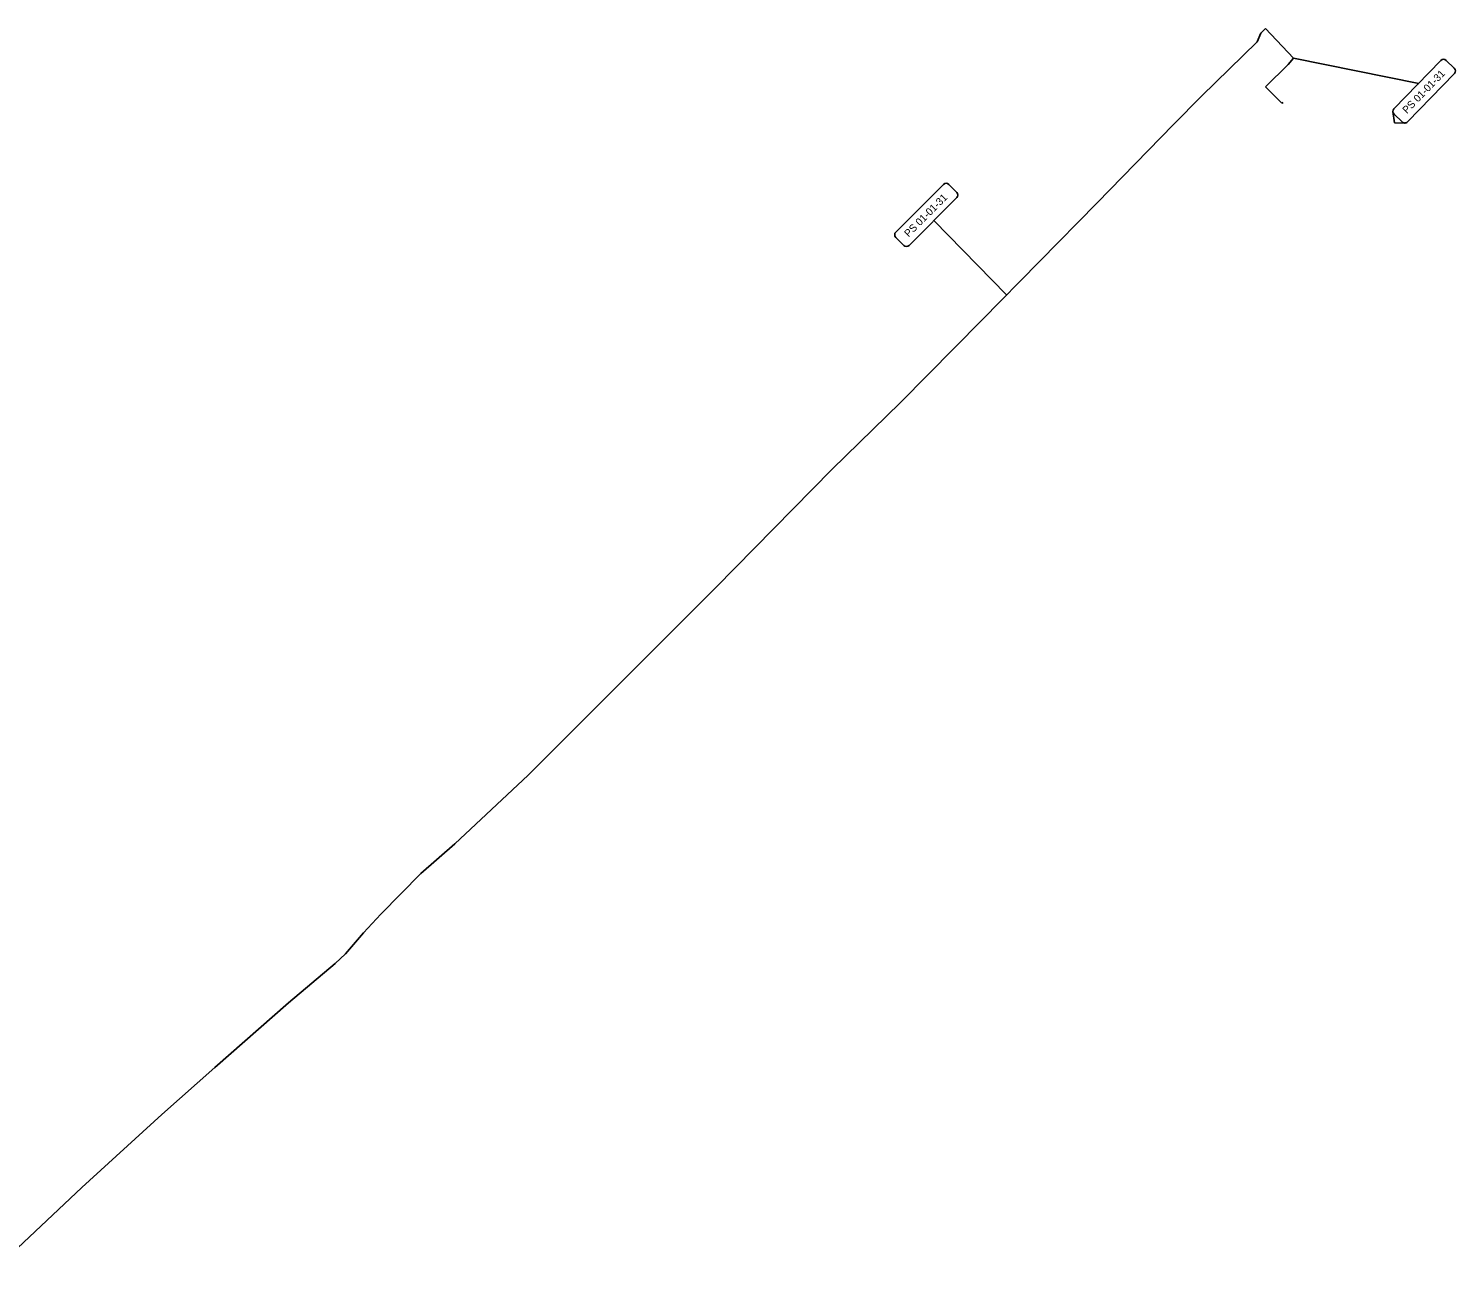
# Model space of a CAD drawing. Extents: x -541464 to -539952, y -1188799 to -1187382.
# Drawn here: x -540701 to -539952, y -1188031 to -1187382 of the extents above; entities that cross this region are included whole.
import ezdxf

# ---------------------------------------------------------------- set-up
doc = ezdxf.new("R2010")
doc.units = 0
doc.layers.add('PS 01-01-31', color=7, linetype='Continuous')

msp = doc.modelspace()

# ---------------------------------------------------------------- linework, layer by layer
at = {"layer": 'PS 01-01-31'}
for p, q in [((-540053.796, -1187384.014), (-540055.837, -1187388.607)), ((-540051.349, -1187381.646), (-540053.796, -1187384.014)), ((-540036.708, -1187397.239), (-540051.349, -1187381.646)), ((-540055.837, -1187388.607), (-540085.066, -1187417.093)), ((-540051.412, -1187412.276), (-540039.488, -1187400.592)), ((-540039.488, -1187400.592), (-540036.708, -1187397.239)), ((-539970.911, -1187410.448), (-540036.708, -1187397.239)), ((-539983.905, -1187423.848), (-539959.24, -1187398.41)), ((-539956.456, -1187398.367), (-539952.216, -1187402.477)), ((-539952.173, -1187405.261), (-539976.838, -1187430.7)), ((-540085.066, -1187417.093), (-540099.657, -1187432.125)), ((-540049.541, -1187414.224), (-540051.412, -1187412.276)), ((-540042.881, -1187420.898), (-540049.541, -1187414.224)), ((-540042.136, -1187420.439), (-540042.881, -1187420.898)), ((-539984.46, -1187425.249), (-539983.663, -1187431.106)), ((-540099.657, -1187432.125), (-540139.811, -1187473.137)), ((-539979.622, -1187430.743), (-539983.861, -1187426.632)), ((-539983.663, -1187431.106), (-539978.221, -1187431.298)), ((-540245.598, -1187488.587), (-540220.537, -1187463.538)), ((-540213.579, -1187470.5), (-540238.641, -1187495.548)), ((-540217.753, -1187463.539), (-540213.578, -1187467.716)), ((-540139.811, -1187473.137), (-540200.425, -1187534.795)), ((-540225.555, -1187482.469), (-540187.374, -1187521.52)), ((-540241.425, -1187495.548), (-540245.599, -1187491.37)), ((-540200.425, -1187534.795), (-540243.107, -1187578.127)), ((-540243.107, -1187578.127), (-540279.202, -1187613.271)), ((-540279.202, -1187613.271), (-540340.21, -1187675.277)), ((-540340.21, -1187675.277), (-540403.608, -1187738.906)), ((-540403.608, -1187738.906), (-540438.749, -1187773.95)), ((-540438.749, -1187773.95), (-540477.233, -1187810.058)), ((-540477.233, -1187810.058), (-540495.127, -1187825.49)), ((-540495.127, -1187825.49), (-540516.103, -1187846.952)), ((-540516.103, -1187846.952), (-540525.206, -1187856.697)), ((-540525.206, -1187856.697), (-540534.706, -1187867.786)), ((-540540.146, -1187872.825), (-540564.538, -1187893.427)), ((-540534.706, -1187867.786), (-540540.146, -1187872.825)), ((-540564.538, -1187893.427), (-540603.22, -1187927.448)), ((-540603.22, -1187927.448), (-540631.102, -1187952.249)), ((-540631.102, -1187952.249), (-540673.211, -1187990.52)), ((-540673.211, -1187990.52), (-540716.275, -1188030.967))]:
    msp.add_line(p, q, dxfattribs=at)
for centre, start, end in [((-539957.827, -1187399.78), 45.884628, 135.884625), ((-539953.587, -1187403.891), 315.884628, 45.884628), ((-539982.492, -1187425.219), 135.884628, 225.884628), ((-539978.252, -1187429.33), 225.884628, 315.884628), ((-540219.146, -1187464.931), 44.984628, 134.984625), ((-540214.971, -1187469.108), 314.984628, 44.984628), ((-540244.207, -1187489.979), 134.984628, 224.984628), ((-540240.033, -1187494.156), 224.984628, 314.984628)]:
    msp.add_arc(centre, 1.969, start, end, dxfattribs=at)

# ---------------------------------------------------------------- texts
for rotation, p in [(45.884608, (-539977.132, -1187426.658)), (44.984608, (-540238.871, -1187491.502))]:
    msp.add_text('PS 01-01-31', height=3.9, rotation=rotation, dxfattribs=at).set_placement(p)

doc.saveas('drawing.dxf')
